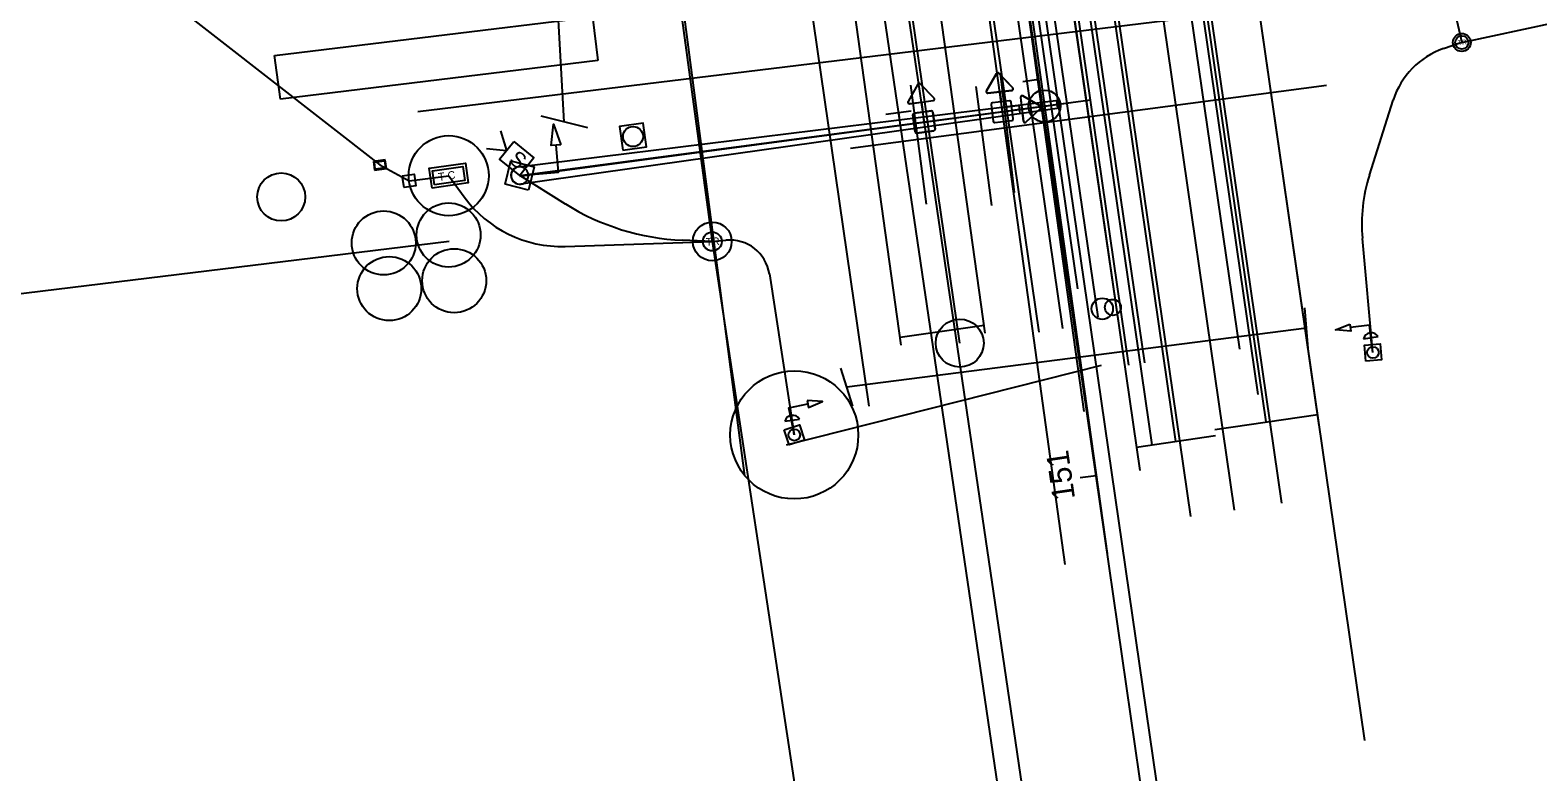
# Model space of a CAD drawing. Extents: x 1827063 to 1831280, y 711192 to 712800.
# Drawn here: x 1828497.6 to 1828686.1, y 711773.6 to 711866.2 of the extents above; entities that cross this region are included whole.
import ezdxf

# ---------------------------------------------------------------- set-up
doc = ezdxf.new("R2010")
doc.units = 0
for name, color, linetype in [('BR_P_Beam_Object', 7, 'Continuous'), ('BR_P_Gen_Joint_Filler', 7, 'Continuous'), ('BR_P_Sub_Centerline', 7, 'Continuous'), ('BR_X_Sub_Object', 7, 'Continuous'), ('Default', 7, 'Continuous'), ('DR_P_Cells', 7, 'Continuous'), ('DR_P_Storm_Sewer', 7, 'Continuous'), ('MT_P_Dotted_Line', 7, 'Continuous'), ('PM_P_Crosswalk', 7, 'Continuous'), ('PV_P_Walk', 7, 'Continuous'), ('PV_X_EOP', 7, 'Continuous'), ('SC_Scratch1', 7, 'Continuous'), ('SC_Shading1', 7, 'Continuous'), ('SG_P_Foundation', 7, 'Continuous'), ('SG_P_Interconnect_Cable', 7, 'Continuous'), ('SG_P_Wiring', 7, 'Continuous'), ('SN_X_Foundation', 7, 'Continuous'), ('TX_P_20', 7, 'Continuous'), ('UT_P_Water', 7, 'Continuous')]:
    doc.layers.add(name, color=color, linetype=linetype)

# ---------------------------------------------------------------- blocks, each defined once
blk = doc.blocks.new('SPOLE_1')
at = {"layer": 'Default'}
blk.add_circle((0, 0), 0.0138, dxfattribs=at)
blk = doc.blocks.new('A$C258B21FD')
at = {"layer": 'Default'}
for p, q in [((1.209, 0.609), (1.307, 1.09)), ((1.307, 1.09), (1.431, 0.61)), ((1.431, 0.61), (1.209, 0.609))]:
    blk.add_line(p, q, dxfattribs=at)
for points in [[(1.431, 0.61), (1.209, 0.609), (1.307, 1.09), (1.431, 0.61)], [(0.442, 0), (1.32, -0.003), (1.32, 0.609)]]:
    blk.add_lwpolyline(points, dxfattribs=at)
blk = doc.blocks.new('A$C140F1C83')
at = {"layer": 'Default'}
for p, q in [((-14.7, 81.2), (38.7, 115.7)), ((45.8, 113.1), (63.9, 52.2)), ((57.7, 46.4), (-13.7, 72.8)), ((22, 59.6), (11, 29.8)), ((-20.4, 36.3), (-39.1, -14.3)), ((36.3, 20.4), (-14.3, 39.1)), ((20.4, -36.3), (39.1, 14.3)), ((46.4, -57.7), (72.8, 13.7)), ((81.2, 14.7), (115.7, -38.7)), ((-36.3, -20.4), (14.3, -39.1)), ((59.6, -22), (29.8, -11)), ((113.1, -45.8), (52.2, -63.9))]:
    blk.add_line(p, q, dxfattribs=at)
for centre, start, end in [((41.2, 111.7), 16.6041, 122.8643), ((-12.1, 77.2), 122.8643, 249.7342), ((59.4, 50.8), 249.7342, 16.6041), ((-16, 34.7), 69.7342, 159.7342), ((34.7, 16), 339.7342, 69.7342), ((77.2, 12.1), 32.8643, 159.7342), ((-34.7, -16), 159.7342, 249.7342), ((16, -34.7), 249.7342, 339.7342), ((111.7, -41.2), 286.6041, 32.8643), ((50.8, -59.4), 159.7342, 286.6041)]:
    blk.add_arc(centre, 4.76, start, end, dxfattribs=at)
blk = doc.blocks.new('Sighead')
at = {"layer": 'Default'}
for p, q in [((-0.03, 0.975), (-0.335, 0.569)), ((0.335, 0.569), (0.03, 0.975)), ((-0.305, 0.508), (0.305, 0.508)), ((0, 0.508), (0, 0.254)), ((-0.254, -0.216), (-0.254, 0.216)), ((-0.216, 0.254), (0.216, 0.254)), ((0.254, 0.216), (0.254, -0.216)), ((0.216, -0.254), (-0.216, -0.254))]:
    blk.add_line(p, q, dxfattribs=at)
for centre, start, end in [((0, 0.953), 36.8699, 143.1301), ((-0.305, 0.546), 143.1301, 270), ((0.305, 0.546), 270, 36.8699), ((-0.216, 0.216), 90, 180), ((0.216, 0.216), 0, 90), ((-0.216, -0.216), 180, 270), ((0.216, -0.216), 270, 0)]:
    blk.add_arc(centre, 0.0381, start, end, dxfattribs=at)
blk = doc.blocks.new('A$C70A22DE5')
at = {"layer": 'Default'}
for p, q in [((0, 0), (0.476, 0)), ((0.476, 0.236), (0.476, -0.236))]:
    blk.add_line(p, q, dxfattribs=at)
blk.add_arc((0.369, 0), 0.259, 294.3601, 65.6399, dxfattribs=at)

msp = doc.modelspace()

# ---------------------------------------------------------------- linework, layer by layer
at = {"layer": 'BR_P_Beam_Object'}
for p, q in [((1828558.69, 711849.17), (1828626.17, 711857.49)), ((1828626.31, 711856.5), (1828558.97, 711847.01)), ((1828626.17, 711857.49), (1828626.31, 711856.5))]:
    msp.add_line(p, q, dxfattribs=at)
msp.add_arc((1828558.83, 711848.09), 1.09, 97.51, 277.51, dxfattribs=at)
at = {"layer": 'BR_P_Gen_Joint_Filler'}
for p, q in [((1828623.75, 711828.52), (1828606.66, 711946.45)), ((1828626.72, 711828.95), (1828609.62, 711946.88)), ((1828633.65, 711829.89), (1828616.56, 711947.82)), ((1828613.82, 711827.13), (1828596.76, 711944.95)), ((1828648.16, 711806.27), (1828628.92, 711939.15)), ((1828654.1, 711807.13), (1828634.86, 711940.01)), ((1828602.5, 711819.24), (1828585.44, 711937.06)), ((1828618.03, 711937.57), (1828636.33, 711811.2)), ((1828642.71, 711805.48), (1828623.48, 711938.36)), ((1828684.74, 711872.92), (1828546.09, 711856.03)), ((1828334.88, 711813.62), (1828550.03, 711839.89))]:
    msp.add_line(p, q, dxfattribs=at)
for centre, radius in [((1828529.02, 711845.39), 3), ((1828549.94, 711840.64), 4), ((1828541.83, 711839.65), 4), ((1828550.64, 711834.93), 4), ((1828542.53, 711833.94), 4), ((1828613.82, 711827.13), 3)]:
    msp.add_circle(centre, radius, dxfattribs=at)
at = {"layer": 'BR_P_Sub_Centerline'}
for centre, radius in [((1828676.57, 711864.7), 1.12), ((1828676.57, 711864.7), 1.12), ((1828676.57, 711864.7), 1.12), ((1828676.57, 711864.7), 0.825), ((1828676.57, 711864.7), 0.825), ((1828676.57, 711864.7), 0.825), ((1828582.9, 711839.83), 2.42), ((1828582.9, 711839.83), 1.18)]:
    msp.add_circle(centre, radius, dxfattribs=at)
at = {"layer": 'BR_X_Sub_Object'}
for p, q in [((1828528.17, 711863.06), (1828567.93, 711867.91)), ((1828567.93, 711867.91), (1828568.59, 711862.45)), ((1828528.94, 711857.62), (1828528.17, 711863.06)), ((1828568.59, 711862.45), (1828528.94, 711857.62)), ((1828556.44, 711853.64), (1828557.19, 711851.21)), ((1828554.66, 711851.43), (1828557.19, 711851.21))]:
    msp.add_line(p, q, dxfattribs=at)
msp.add_lwpolyline([(1828558.08, 711852.32), (1828560.61, 711850.28), (1828558.83, 711848.07), (1828556.3, 711850.11)], close=True, dxfattribs=at)
at = {"layer": 'DR_P_Cells'}
for points in [[(1828664.56, 711824.88), (1828664.4, 711826.88), (1828666.39, 711827.03), (1828666.55, 711825.04)], [(1828591.9, 711816.31), (1828593.8, 711816.92), (1828594.41, 711815.02), (1828592.51, 711814.41)]]:
    msp.add_lwpolyline(points, close=True, dxfattribs=at)
for centre in [(1828665.47, 711825.96), (1828593.15, 711815.66)]:
    msp.add_circle(centre, 0.727, dxfattribs=at)
at = {"layer": 'DR_P_Storm_Sewer'}
for p, q in [((1828720.42, 711192.02), (1828611.37, 711945.24)), ((1828623.7, 711860.06), (1828621.72, 711859.77)), ((1828630.86, 711810.57), (1828628.88, 711810.29))]:
    msp.add_line(p, q, dxfattribs=at)
at = {"layer": 'MT_P_Dotted_Line'}
for p, q in [((1828604.6, 711855.72), (1828607.77, 711856.14)), ((1828606.18, 711855.93), (1828606.39, 711854.34))]:
    msp.add_line(p, q, dxfattribs=at)
at = {"layer": 'PM_P_Crosswalk'}
for p, q in [((1828652.12, 711817.28), (1828623.47, 712015.21)), ((1828658.75, 711816.84), (1828637.26, 711965.29)), ((1828640.85, 711814.86), (1828619.36, 711963.31)), ((1828637.88, 711814.43), (1828616.39, 711962.88)), ((1828611.42, 711949.41), (1828632.25, 711800.86)), ((1828606.4, 711948.06), (1828626.95, 711799.47)), ((1828592.98, 711945.4), (1828622.13, 711747.54)), ((1828595.95, 711945.84), (1828625.09, 711747.97)), ((1828558.84, 711847.97), (1828627.73, 711857.19)), ((1828619.05, 711856.57), (1828621.04, 711856.81)), ((1828619.05, 711856.57), (1828619.2, 711855.54)), ((1828626.17, 711857.49), (1828626.31, 711856.5)), ((1828609.27, 711855.37), (1828609.45, 711854.16)), ((1828645.69, 711816.35), (1828658.56, 711818.21)), ((1828635.9, 711814.15), (1828645.8, 711815.58))]:
    msp.add_line(p, q, dxfattribs=at)
msp.add_circle((1828624.42, 711856.75), 2, dxfattribs=at)
at = {"layer": 'PV_P_Walk'}
for p, q in [((1828722.4, 711192.31), (1828579.11, 712181.99)), ((1828631.11, 711830.4), (1828612.66, 711957.67)), ((1828628.58, 711833.92), (1828610.68, 711957.38)), ((1828606.51, 711826.86), (1828590.3, 711942.89)), ((1828617.02, 711828.39), (1828600.91, 711943.74)), ((1828632.16, 711941.22), (1828648.78, 711826.37)), ((1828618.3, 711939.2), (1828634.93, 711824.36)), ((1828620.28, 711939.48), (1828636.91, 711824.65)), ((1828664.45, 711777.49), (1828644.18, 711917.51)), ((1828606.36, 711827.89), (1828616.88, 711829.36)), ((1828592.18, 711814.44), (1828631.55, 711824.37))]:
    msp.add_line(p, q, dxfattribs=at)
for centre, radius in [((1828549.96, 711848.05), 5), ((1828631.64, 711831.42), 1.33), ((1828632.96, 711831.6), 1), ((1828593.15, 711815.66), 8)]:
    msp.add_circle(centre, radius, dxfattribs=at)
at = {"layer": 'PV_X_EOP'}
for p, q in [((1828608.58, 711967.13), (1828629.33, 711818.57)), ((1828569.28, 711944.95), (1828586.92, 711810.54)), ((1828651.12, 711820.7), (1828637.64, 711913.82)), ((1828564.38, 711854.79), (1828561.88, 711899.08)), ((1828558.83, 711848.07), (1828625.99, 711856.96)), ((1828625.92, 711857.45), (1828626.06, 711856.46)), ((1828561.45, 711855.53), (1828567.3, 711854.05)), ((1828657.36, 711826.48), (1828656.96, 711831.52)), ((1828657.16, 711829), (1828599.71, 711821.63)), ((1828600.47, 711819.25), (1828598.95, 711824.01))]:
    msp.add_line(p, q, dxfattribs=at)
at = {"layer": 'SC_Scratch1'}
for p, q in [((1828620.65, 711845.94), (1828618.9, 711860.84)), ((1828600.17, 711851.49), (1828659.65, 711859.37)), ((1828609.67, 711844.5), (1828607.71, 711859.37)), ((1828617.82, 711844.31), (1828615.87, 711859.18)), ((1828558.83, 711848.07), (1828630.21, 711857.52)), ((1828621.22, 711856.83), (1828621.35, 711855.84))]:
    msp.add_line(p, q, dxfattribs=at)
at = {"layer": 'SC_Shading1'}
msp.add_lwpolyline([(1828547.88, 711846.49), (1828547.53, 711848.97), (1828552.04, 711849.61), (1828552.39, 711847.14), (1828547.88, 711846.49)], dxfattribs=at)
for points in [[(1828548.18, 711846.89), (1828547.93, 711848.67), (1828551.74, 711849.21), (1828551.99, 711847.44)], [(1828544.15, 711848.04), (1828545.64, 711848.26), (1828545.85, 711846.77), (1828544.37, 711846.56)]]:
    msp.add_lwpolyline(points, close=True, dxfattribs=at)
at = {"layer": 'SG_P_Foundation'}
for p, q in [((1828557.01, 711846.98), (1828557.74, 711849.89)), ((1828557.74, 711849.89), (1828560.65, 711849.16)), ((1828560.65, 711849.16), (1828559.92, 711846.24)), ((1828559.92, 711846.24), (1828557.01, 711846.98))]:
    msp.add_line(p, q, dxfattribs=at)
for start, end in [(165.8266, 345.8266), (345.8266, 165.8266)]:
    msp.add_arc((1828558.83, 711848.07), 1.09, start, end, dxfattribs=at)
at = {"layer": 'SG_P_Interconnect_Cable'}
msp.add_line((1828582.9, 711839.83), (1828615.75, 711622.86), dxfattribs=at)
at = {"layer": 'SG_P_Wiring'}
for p, q in [((1828660.68, 711934.76), (1828676.57, 711864.7)), ((1828572.85, 711913.24), (1828582.9, 711839.83)), ((1828502.32, 711879.81), (1828541.36, 711849.39)), ((1828676.57, 711864.7), (1828688.2, 711867.2)), ((1828674.27, 711863.93), (1828676.34, 711864.64)), ((1828674.27, 711863.93), (1828676.34, 711864.64)), ((1828676.34, 711864.64), (1828676.57, 711864.7)), ((1828665.02, 711848.11), (1828668.01, 711857.5)), ((1828665.02, 711848.11), (1828668.01, 711857.5)), ((1828541.36, 711849.39), (1828545, 711847.41)), ((1828545, 711847.41), (1828549.96, 711848.05)), ((1828549.96, 711848.05), (1828551.89, 711845.4)), ((1828564.55, 711844.51), (1828558.83, 711848.09)), ((1828564.52, 711839.22), (1828582.9, 711839.83)), ((1828582.9, 711839.83), (1828579.17, 711839.98)), ((1828582.9, 711839.83), (1828584.61, 711839.99)), ((1828665.47, 711825.96), (1828664.16, 711840.22)), ((1828665.47, 711825.96), (1828664.16, 711840.22)), ((1828590.03, 711835.78), (1828593.15, 711815.66))]:
    msp.add_line(p, q, dxfattribs=at)
for centre, radius, start, end in [((1828677.54, 711854.47), 10, 109.0486, 162.3657), ((1828677.54, 711854.47), 10, 109.0486, 162.3657), ((1828684.08, 711842.05), 20, 162.3657, 185.2396), ((1828684.08, 711842.05), 20, 162.3657, 185.2396), ((1828564.03, 711854.21), 15, 215.9872, 271.8931), ((1828580.45, 711869.96), 30, 238.0136, 267.5602), ((1828585.09, 711835.01), 5, 8.8224, 95.509)]:
    msp.add_arc(centre, radius, start, end, dxfattribs=at)
at = {"layer": 'SN_X_Foundation'}
msp.add_lwpolyline([(1828571.71, 711851.24), (1828574.68, 711851.66), (1828574.26, 711854.63), (1828571.29, 711854.21)], close=True, dxfattribs=at)
msp.add_circle((1828572.99, 711852.94), 1.25, dxfattribs=at)
at = {"layer": 'TX_P_20'}
for p, q in [((1828542.03, 711850.02), (1828540.55, 711849.83)), ((1828540.55, 711849.83), (1828540.69, 711848.76)), ((1828540.67, 711849.73), (1828541.94, 711849.9)), ((1828540.78, 711848.88), (1828540.67, 711849.73)), ((1828540.69, 711848.76), (1828542.17, 711848.95)), ((1828542.05, 711849.05), (1828540.78, 711848.88)), ((1828541.94, 711849.9), (1828542.05, 711849.05)), ((1828542.17, 711848.95), (1828542.03, 711850.02))]:
    msp.add_line(p, q, dxfattribs=at)
at = {"layer": 'UT_P_Water'}
for p, q in [((1828608.59, 711859.5), (1828607.36, 711857.32)), ((1828610.63, 711857.75), (1828608.88, 711859.54)), ((1828620.32, 711858.71), (1828620.32, 711858.71)), ((1828610.74, 711853.87), (1828610.46, 711855.98)), ((1828617.92, 711857.17), (1828617.92, 711857.17)), ((1828607.98, 711855.65), (1828608.26, 711853.55)), ((1828608.47, 711853.38), (1828610.58, 711853.66))]:
    msp.add_line(p, q, dxfattribs=at)
for points in [[(1828618.42, 711860.8), (1828617.16, 711858.64)], [(1828620.44, 711859.03), (1828618.71, 711860.84)], [(1828617.34, 711858.36), (1828620.32, 711858.71), (1828620.32, 711858.71)], [(1828621.43, 711857.83), (1828621.78, 711854.85), (1828621.78, 711854.85)], [(1828623.87, 711856.76), (1828621.71, 711858.02)], [(1828607.55, 711857.05), (1828609.04, 711857.24), (1828610.52, 711857.44)], [(1828610.25, 711856.14), (1828609.2, 711856), (1828608.15, 711855.86)], [(1828617.76, 711856.96), (1828618.01, 711854.85)], [(1828620.03, 711857.42), (1828617.92, 711857.17), (1828617.92, 711857.17)], [(1828620.49, 711855.14), (1828620.24, 711857.25)], [(1828622.1, 711854.74), (1828623.91, 711856.46)], [(1828618.22, 711854.69), (1828620.33, 711854.93)]]:
    msp.add_lwpolyline(points, dxfattribs=at)
for centre, start, end in [((1828608.75, 711859.41), 44.3636, 150.6238), ((1828618.58, 711860.71), 43.5833, 149.8435), ((1828610.5, 711857.62), 277.4937, 44.3636), ((1828617.32, 711858.55), 149.8435, 276.7134), ((1828620.3, 711858.9), 276.7134, 43.5833), ((1828621.62, 711857.86), 59.8435, 186.7134), ((1828607.52, 711857.23), 150.6238, 277.4937), ((1828608.17, 711855.68), 97.4937, 187.4937), ((1828610.28, 711855.95), 7.4937, 97.4937), ((1828617.95, 711856.98), 96.7134, 186.7134), ((1828620.06, 711857.23), 6.7134, 96.7134), ((1828623.78, 711856.6), 313.5833, 59.8435), ((1828618.19, 711854.87), 186.7134, 276.7134), ((1828620.3, 711855.12), 276.7134, 6.7134), ((1828621.97, 711854.88), 186.7134, 313.5833), ((1828608.45, 711853.57), 187.4937, 277.4937), ((1828610.55, 711853.85), 277.4937, 7.4937)]:
    msp.add_arc(centre, 0.187, start, end, dxfattribs=at)

# ---------------------------------------------------------------- block references
at = {"layer": 'BR_X_Sub_Object'}
for p, xscale, yscale, rotation in [((1828665.47, 711825.96), 3.941724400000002, 3.941724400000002, 98.23492600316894), ((1828593.15, 711815.66), 3.9417244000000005, 3.9417244, 98.25498678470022)]:
    msp.add_blockref('A$C70A22DE5', p, dxfattribs=dict(at, xscale=xscale, yscale=yscale, rotation=rotation))
at = {"layer": 'DR_P_Cells', "yscale": 52.495541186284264}
for p, xscale, rotation in [((1828665.47, 711825.96), 52.49554118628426, 94.56738338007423), ((1828593.15, 711815.66), 52.49554118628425, 17.73779086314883)]:
    msp.add_blockref('SPOLE_1', p, dxfattribs=dict(at, xscale=xscale, rotation=rotation))
at = {"layer": 'UT_P_Water'}
for name, p, xscale, yscale, rotation in [('A$C140F1C83', (1828619.13, 711856.05), 0.03936999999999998, 0.03936999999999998, 26.97921368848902), ('Sighead', (1828609.36, 711854.76), 4.921250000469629, 4.921250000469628, 7.493655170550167), ('A$C258B21FD', (1828556.39, 711847.85), 5.536236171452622, 5.536236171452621, 5.086785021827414), ('A$C258B21FD', (1828665.69, 711824.23), 3.937, 3.9370000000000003, 97.30964975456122), ('A$C258B21FD', (1828593.5, 711813.96), 3.937000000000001, -3.9370000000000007, 101.42358785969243)]:
    msp.add_blockref(name, p, dxfattribs=dict(at, xscale=xscale, yscale=yscale, rotation=rotation))

# ---------------------------------------------------------------- texts
at = {"layer": 'BR_P_Sub_Centerline'}
for height, rotation, p in [(0.591, 7.7982, (1828676.13, 711864.34)), (0.962, 3.7551, (1828582.13, 711839.29))]:
    msp.add_text('TR', height=height, rotation=rotation, dxfattribs=at).set_placement(p)
at = {"layer": 'BR_X_Sub_Object'}
msp.add_text('S', height=1.95, rotation=321.1366, dxfattribs=at).set_placement((1828557.34, 711849.84))
at = {"layer": 'DR_P_Storm_Sewer'}
msp.add_text('151', height=2.8, rotation=98.238, dxfattribs=at).set_placement((1828628.25, 711807.71))
at = {"layer": 'SC_Shading1'}
msp.add_text('T C', height=0.996, rotation=8.0994, dxfattribs=at).set_placement((1828548.72, 711847.38))

doc.saveas('drawing.dxf')
